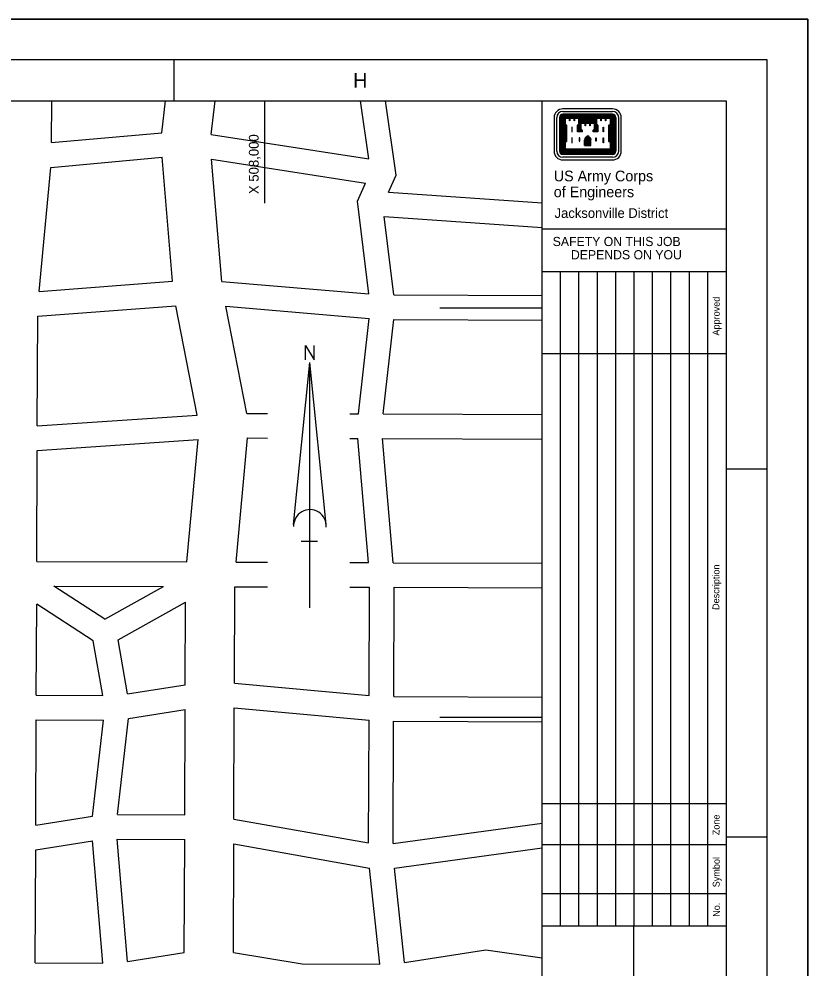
# Model space of a CAD drawing. Extents: x 501128 to 509328, y 1314906 to 1320706.
# Drawn here: x 507399 to 509328, y 1318384 to 1320706 of the extents above; entities that cross this region are included whole.
import ezdxf

# ---------------------------------------------------------------- set-up
doc = ezdxf.new("R2010")
doc.units = 0
for name, color, linetype in [('G-ANNO-SYMB', 7, 'Continuous'), ('G-ANNO-TEXT', 7, 'Continuous'), ('G-ANNO-TTLB', 7, 'Continuous'), ('Level 14', 7, 'Continuous'), ('Level 2', 7, 'Continuous'), ('Level 3', 7, 'Continuous'), ('Level 32', 7, 'Continuous')]:
    doc.layers.add(name, color=color, linetype=linetype)

msp = doc.modelspace()

# ---------------------------------------------------------------- linework, layer by layer
at = {"layer": 'G-ANNO-SYMB'}
for p, q in [((508850.3, 1320486.7), (508728.7, 1320486.7)), ((508728.7, 1320480.3), (508850.3, 1320480.3)), ((508850.3, 1320473.5), (508728.7, 1320473.5)), ((508707.3, 1320465.3), (508707.3, 1320383.3)), ((508713.7, 1320383.3), (508713.7, 1320465.3)), ((508720.7, 1320465.3), (508720.7, 1320383.3)), ((508722.5, 1320465.3), (508722.5, 1320383.3)), ((508724.1, 1320465.3), (508724.1, 1320383.3)), ((508725.9, 1320465.3), (508725.9, 1320383.3)), ((508727.7, 1320465.3), (508727.7, 1320383.3)), ((508850.3, 1320471.7), (508728.7, 1320471.7)), ((508850.3, 1320469.9), (508728.7, 1320469.9)), ((508850.3, 1320468.3), (508728.7, 1320468.3)), ((508850.3, 1320466.5), (508728.7, 1320466.5)), ((508729.5, 1320465.3), (508729.5, 1320383.9)), ((508731.1, 1320465.3), (508731.1, 1320385.7)), ((508770.9, 1320464.9), (508808.1, 1320464.9)), ((508770.9, 1320463.1), (508808.1, 1320463.1)), ((508770.9, 1320461.5), (508808.1, 1320461.5)), ((508770.9, 1320459.7), (508808.1, 1320459.7)), ((508770.9, 1320457.9), (508808.1, 1320457.9)), ((508770.9, 1320456.3), (508808.1, 1320456.3)), ((508770.9, 1320454.5), (508808.1, 1320454.5)), ((508847.9, 1320465.3), (508847.9, 1320385.7)), ((508849.5, 1320465.3), (508849.5, 1320383.9)), ((508851.3, 1320465.3), (508851.3, 1320383.3)), ((508853.1, 1320465.3), (508853.1, 1320383.3)), ((508854.7, 1320465.3), (508854.7, 1320383.3)), ((508856.5, 1320465.3), (508856.5, 1320383.3)), ((508858.3, 1320465.3), (508858.3, 1320383.3)), ((508865.1, 1320465.3), (508865.1, 1320383.3)), ((508871.7, 1320383.3), (508871.7, 1320465.3)), ((508732.5, 1320447.9), (508732.5, 1320405.9)), ((508734.3, 1320446.1), (508734.3, 1320407.9)), ((508844.7, 1320446.1), (508844.7, 1320407.9)), ((508846.5, 1320447.7), (508846.5, 1320406.1)), ((508781.5, 1320397.5), (508781.5, 1320410.9)), ((508783.1, 1320397.5), (508783.1, 1320410.9)), ((508784.9, 1320397.5), (508784.9, 1320410.9)), ((508786.7, 1320397.5), (508786.7, 1320410.9)), ((508788.3, 1320397.5), (508788.3, 1320410.9)), ((508790.7, 1320397.5), (508790.7, 1320410.9)), ((508792.3, 1320397.5), (508792.3, 1320410.9)), ((508794.1, 1320397.5), (508794.1, 1320410.9)), ((508795.9, 1320397.5), (508795.9, 1320410.9)), ((508797.5, 1320397.5), (508797.5, 1320410.9)), ((508850.3, 1320382.1), (508728.7, 1320382.1)), ((508850.3, 1320380.5), (508728.7, 1320380.5)), ((508849.5, 1320383.9), (508729.5, 1320383.9)), ((508847.9, 1320385.7), (508731.1, 1320385.7)), ((508781.5, 1320397.5), (508797.5, 1320397.5)), ((508850.3, 1320378.7), (508728.7, 1320378.7)), ((508850.3, 1320376.9), (508728.7, 1320376.9)), ((508850.3, 1320375.3), (508728.7, 1320375.3)), ((508850.3, 1320368.3), (508728.7, 1320368.3)), ((508728.7, 1320361.7), (508850.3, 1320361.7))]:
    msp.add_line(p, q, dxfattribs=at)
for points in [[(508732.5, 1320465.3), (508732.5, 1320449.5), (508735.9, 1320446.1), (508735.9, 1320407.9), (508732.5, 1320404.3), (508732.5, 1320386.9), (508846.5, 1320386.9), (508846.5, 1320404.3), (508842.9, 1320407.9), (508842.9, 1320446.1), (508846.5, 1320449.5), (508846.5, 1320465.3), (508831.5, 1320465.3), (508819.9, 1320465.3), (508809.1, 1320465.3), (508809.1, 1320449.5), (508812.9, 1320446.1), (508812.9, 1320432.1), (508804.5, 1320432.1), (508804.5, 1320433.5), (508808.1, 1320437.1), (508808.1, 1320452.7), (508793.1, 1320452.7), (508781.5, 1320452.7), (508770.9, 1320452.7), (508770.9, 1320437.1), (508774.5, 1320433.5), (508774.5, 1320432.1), (508766.1, 1320432.1), (508766.1, 1320446.1), (508769.7, 1320449.5), (508769.7, 1320465.3), (508754.7, 1320465.3), (508743.1, 1320465.3), (508732.5, 1320465.3)], [(508734.1, 1320463.5), (508734.1, 1320450.3), (508737.7, 1320446.7), (508737.7, 1320407.1), (508734.1, 1320403.5), (508734.1, 1320388.7), (508844.9, 1320388.7), (508844.9, 1320403.5), (508841.1, 1320407.1), (508841.1, 1320446.7), (508844.9, 1320450.3), (508844.9, 1320463.5), (508834.1, 1320463.5), (508834.1, 1320457.3), (508833.1, 1320457.3), (508833.1, 1320463.5), (508822.5, 1320463.5), (508822.5, 1320457.3), (508821.7, 1320457.3), (508821.7, 1320463.5), (508810.9, 1320463.5), (508810.9, 1320450.3), (508814.5, 1320446.7), (508814.5, 1320430.5), (508802.9, 1320430.5), (508802.9, 1320434.3), (508806.5, 1320437.9), (508806.5, 1320451.1), (508795.7, 1320451.1), (508795.7, 1320444.9), (508794.9, 1320444.9), (508794.9, 1320451.1), (508784.1, 1320451.1), (508784.1, 1320444.9), (508783.1, 1320444.9), (508783.1, 1320451.1), (508772.5, 1320451.1), (508772.5, 1320437.9), (508776.1, 1320434.3), (508776.1, 1320430.5), (508764.5, 1320430.5), (508764.5, 1320446.7), (508768.1, 1320450.3), (508768.1, 1320463.5), (508757.5, 1320463.5), (508757.5, 1320457.3), (508756.5, 1320457.3), (508756.5, 1320463.5), (508745.7, 1320463.5), (508745.7, 1320457.3), (508744.9, 1320457.3), (508744.9, 1320463.5), (508734.1, 1320463.5)], [(508750.5, 1320442.1), (508750.5, 1320430.5), (508751.7, 1320430.5), (508751.7, 1320442.1), (508750.5, 1320442.1)], [(508768.9, 1320446.3), (508767.9, 1320445.3), (508767.9, 1320433.9), (508771.7, 1320433.9), (508769.1, 1320436.5), (508769.1, 1320446.5)], [(508810.1, 1320446.3), (508811.1, 1320445.3), (508811.1, 1320433.9), (508807.5, 1320433.9), (508809.9, 1320436.5), (508809.9, 1320446.5)], [(508828.3, 1320442.1), (508828.3, 1320430.5), (508827.3, 1320430.5), (508827.3, 1320442.1), (508828.3, 1320442.1)], [(508750.5, 1320415.5), (508750.5, 1320403.7), (508751.7, 1320403.7), (508751.7, 1320415.5), (508750.5, 1320415.5)], [(508768.9, 1320415.5), (508768.9, 1320407.3), (508769.9, 1320407.3), (508769.9, 1320415.5), (508768.9, 1320415.5)], [(508810.1, 1320415.5), (508810.1, 1320407.3), (508809.1, 1320407.3), (508809.1, 1320415.5), (508810.1, 1320415.5)], [(508828.3, 1320415.5), (508828.3, 1320403.7), (508827.3, 1320403.7), (508827.3, 1320415.5), (508828.3, 1320415.5)]]:
    msp.add_lwpolyline(points, dxfattribs=at)
for centre, major_axis, start_param, end_param in [((508728.8, 1320465.3), (21.4, 0), 1.57078, 3.141576), ((508728.8, 1320465.3), (15, 0), 1.57078, 3.141576), ((508728.8, 1320465.3), (8.04, 0), 1.57078, 3.141576), ((508850.2, 1320465.3), (21.4, 0), 6.283169, 7.853965), ((508850.2, 1320465.3), (15, 0), 6.28317, 7.853966), ((508850.2, 1320465.3), (8.04, 0), 6.283169, 7.853965), ((508728.8, 1320465.3), (6.3, 0), 1.57078, 3.141576), ((508728.8, 1320465.3), (4.56, 0), 1.57078, 3.141576), ((508728.8, 1320465.3), (2.83, 0), 1.57078, 3.141576), ((508728.8, 1320465.3), (1.09, 0), 1.57078, 3.141576), ((508850.2, 1320465.3), (6.3, 0), 6.283169, 7.853965), ((508850.2, 1320465.3), (4.56, 0), 6.283169, 7.853965), ((508850.2, 1320465.3), (2.83, 0), 6.283169, 7.853965), ((508850.2, 1320465.3), (1.09, 0), 6.283169, 7.853965), ((508792.5, 1320410), (-11.1, 0), 4.985832, 6.214359), ((508792.5, 1320410), (-9.37, 0), 4.947465, 6.21436), ((508792.5, 1320410), (-7.63, 0), 4.947465, 6.21436), ((508792.5, 1320410), (-5.9, 0), 4.947465, 6.21436), ((508786.5, 1320410), (4.16, 0), 0.068794, 1.335689), ((508786.5, 1320410), (5.9, 0), 0.068794, 1.335689), ((508786.5, 1320410), (7.63, 0), 0.068795, 1.335689), ((508792.5, 1320410), (-4.16, 0), 4.947465, 6.214359), ((508786.5, 1320410), (9.37, 0), 0.068795, 1.335689), ((508786.5, 1320410), (11.1, 0), 0.068795, 1.29842), ((508728.8, 1320383.2), (-21.4, 0), 6.28317, 7.853966), ((508728.8, 1320383.2), (-15, 0), 6.28317, 7.853966), ((508728.8, 1320383.2), (-8.04, 0), 6.28317, 7.853966), ((508728.8, 1320383.2), (-6.3, 0), 6.28317, 7.853966), ((508728.8, 1320383.2), (-4.56, 0), 6.28317, 7.853966), ((508728.8, 1320383.2), (-2.83, 0), 6.28317, 7.853966), ((508728.8, 1320383.2), (-1.09, 0), 6.28317, 7.853966), ((508850.2, 1320383.2), (8.04, 0), 4.712373, 6.28317), ((508850.2, 1320383.2), (6.3, 0), 4.712373, 6.28317), ((508850.2, 1320383.2), (4.56, 0), 4.712373, 6.28317), ((508850.2, 1320383.2), (2.83, 0), 4.712373, 6.28317), ((508850.2, 1320383.2), (1.09, 0), 4.712373, 6.28317), ((508850.2, 1320383.2), (21.4, 0), 4.712373, 6.28317), ((508850.2, 1320383.2), (-15, 0), 1.570781, 3.141577)]:
    msp.add_ellipse(centre, major_axis=major_axis, ratio=0.99964, start_param=start_param, end_param=end_param, dxfattribs=at)
at = {"layer": 'G-ANNO-TTLB'}
for p, q in [((509228.1, 1320606.3), (501228.1, 1320606.3)), ((507778.1, 1320506.3), (507778.1, 1320606.3)), ((509228.1, 1315006.3), (509228.1, 1320606.3)), ((501478.1, 1320506.3), (509128.1, 1320506.3)), ((508678.1, 1315106.3), (508678.1, 1320506.3)), ((509128.1, 1320506.3), (509128.1, 1315106.3)), ((509128.1, 1320192.9), (508678.1, 1320192.9)), ((508723.1, 1318488.9), (508723.1, 1320088.7)), ((508768.1, 1318488.9), (508768.1, 1320088.7)), ((508813.1, 1318488.9), (508813.1, 1320088.7)), ((508858.1, 1318488.9), (508858.1, 1320088.7)), ((508903.1, 1318488.9), (508903.1, 1320088.7)), ((508948.1, 1318488.9), (508948.1, 1320088.7)), ((508993.1, 1318488.9), (508993.1, 1320088.7)), ((509038.1, 1318488.9), (509038.1, 1320088.7)), ((509083.1, 1318488.9), (509083.1, 1320088.7)), ((508678.1, 1319888.7), (509128.1, 1319888.7)), ((509228.1, 1319606.3), (509128.1, 1319606.3)), ((508678.1, 1318788.9), (509128.1, 1318788.9)), ((508678.1, 1318688.9), (509128.1, 1318688.9)), ((509228.1, 1318706.3), (509128.1, 1318706.3)), ((508678.1, 1318568.9), (509128.1, 1318568.9)), ((508901.5, 1318488.9), (508901.5, 1317449.1))]:
    msp.add_line(p, q, dxfattribs=at)
for points in [[(501128.1, 1314906.3), (509328.1, 1314906.3), (509328.1, 1320706.3), (501128.1, 1320706.3)], [(501128.1, 1314906.3), (509328.1, 1314906.3), (509328.1, 1320706.3), (501128.1, 1320706.3)], [(501128.1, 1320706.3), (509328.1, 1320706.3), (509328.1, 1314906.3), (501128.1, 1314906.3)]]:
    msp.add_lwpolyline(points, close=True, dxfattribs=at)
for points in [[(509278.1, 1320706.3), (509328.1, 1320706.3), (509328.1, 1320656.3)], [(509128.1, 1320088.7), (508678.1, 1320088.7)], [(509128.1, 1318488.9), (508678.1, 1318488.9)]]:
    msp.add_lwpolyline(points, dxfattribs=at)
at = {"layer": 'Level 14'}
for p, q in [((507478.7, 1320404.1), (507479.1, 1320506.3)), ((507748.5, 1320428.4), (507757.5, 1320506.3)), ((507868.8, 1320424.2), (507878.3, 1320506.3)), ((507774.6, 1320065.1), (507748.8, 1320368.2)), ((507895, 1320065), (507869.7, 1320363.4)), ((507448.4, 1320040.1), (507476.5, 1320343.7)), ((507834.2, 1319738.1), (507782.5, 1320005.6)), ((507955.7, 1319742.2), (507905, 1320004)), ((507443.8, 1319712.1), (507444.8, 1319979.7)), ((507809.2, 1319379.2), (507836.9, 1319678.1)), ((507929.7, 1319378.7), (507957.8, 1319682.2)), ((507442.5, 1319380.6), (507443.6, 1319651.9)), ((507925.7, 1319082.8), (507926.5, 1319318.7)), ((507441.3, 1319053.4), (507442.2, 1319276.3)), ((507805.6, 1319079.1), (507806.4, 1319281)), ((507804.4, 1318761.2), (507805.4, 1319018.3)), ((507924.4, 1318750.8), (507925.4, 1319022.6)), ((507440.1, 1318736.2), (507441.1, 1318993.4)), ((507803.2, 1318424.7), (507804.2, 1318701.2)), ((507923.2, 1318424.2), (507924.2, 1318689.9)), ((507438.8, 1318399), (507439.9, 1318675.4))]:
    msp.add_line(p, q, dxfattribs=at)
at = {"layer": 'Level 2'}
for p, q in [((508000, 1320256.3), (508000, 1320506.3)), ((508428.1, 1320000), (508678.1, 1320000)), ((508070.5, 1319471.1), (508110.3, 1319867.1)), ((508110.3, 1319267.1), (508110.3, 1319867.1)), ((508150.1, 1319471.1), (508110.3, 1319867.1)), ((508129.2, 1319429.1), (508089.2, 1319429.1)), ((508428.1, 1319000), (508678.1, 1319000))]:
    msp.add_line(p, q, dxfattribs=at)
msp.add_lwpolyline([(508099.2, 1319873.5), (508099.2, 1319908.5), (508121, 1319873.5), (508121, 1319908.5)], dxfattribs=at)
msp.add_arc((508110.3, 1319467.1), 40, 355.2984, 182.0673, dxfattribs=at)
at = {"layer": 'Level 32'}
for p, q in [((508254.5, 1320364.8), (508234.1, 1320506.3)), ((508320.9, 1320324.6), (508294.7, 1320506.3)), ((507478.7, 1320404.1), (507748.5, 1320428.4)), ((507868.8, 1320424.2), (508254.5, 1320364.8)), ((507476.5, 1320343.7), (507748.8, 1320368.2)), ((507869.7, 1320363.4), (508246.5, 1320305.3)), ((508302.4, 1320283.3), (508320.9, 1320324.6)), ((508226.6, 1320261), (508246.5, 1320305.3)), ((508302.4, 1320283.3), (508678.1, 1320257)), ((508254.5, 1320034.8), (508226.6, 1320261)), ((508315.3, 1320031.7), (508291.7, 1320223.9)), ((508291.7, 1320223.9), (508678.1, 1320196.9)), ((507448.4, 1320040.1), (507774.6, 1320065.1)), ((507895, 1320065), (508254.5, 1320034.8)), ((508315.3, 1320031.7), (508678.1, 1320030.3)), ((507444.8, 1319979.7), (507782.5, 1320005.6)), ((507905, 1320004), (508255.4, 1319974.5)), ((508228.7, 1319741.2), (508255.4, 1319974.5)), ((508289, 1319740.9), (508315.5, 1319971.7)), ((508315.5, 1319971.7), (508678.1, 1319970.3)), ((507443.8, 1319712.1), (507834.2, 1319738.1)), ((507955.7, 1319742.2), (508006.4, 1319742)), ((508208.1, 1319741.2), (508228.7, 1319741.2)), ((508289, 1319740.9), (508678.1, 1319739.5)), ((507443.6, 1319651.9), (507836.9, 1319678.1)), ((507957.8, 1319682.2), (508006.4, 1319682)), ((508208.1, 1319681.2), (508227.8, 1319681.2)), ((508253.6, 1319377.5), (508227.8, 1319681.2)), ((508313.9, 1319377.3), (508288.1, 1319680.9)), ((508288.1, 1319680.9), (508678.1, 1319679.5)), ((507442.5, 1319380.6), (507809.2, 1319379.2)), ((507929.7, 1319378.7), (508006.4, 1319378.4)), ((508208.1, 1319377.7), (508253.6, 1319377.5)), ((508313.9, 1319377.3), (508678.1, 1319375.9)), ((507609, 1319239.5), (507484.4, 1319320.4)), ((507484.4, 1319320.4), (507752.1, 1319319.4)), ((507609, 1319239.5), (507752.1, 1319319.4)), ((507926.5, 1319318.7), (508006.4, 1319318.4)), ((508208.1, 1319317.7), (508256.2, 1319317.5)), ((508255.2, 1319053), (508256.2, 1319317.5)), ((508315.2, 1319050.1), (508316.2, 1319317.3)), ((508316.2, 1319317.3), (508678.1, 1319315.9)), ((507580.5, 1319186.5), (507442.2, 1319276.3)), ((507641.1, 1319188.7), (507806.4, 1319281)), ((507603.8, 1319052.8), (507580.5, 1319186.5)), ((507664, 1319056.8), (507641.1, 1319188.7)), ((507925.7, 1319082.8), (508255.2, 1319053)), ((507664, 1319056.8), (507805.6, 1319079.1)), ((507441.3, 1319053.4), (507603.8, 1319052.8)), ((508315.2, 1319050.1), (508678.1, 1319048.7)), ((507666.7, 1318996.5), (507805.4, 1319018.3)), ((507925.4, 1319022.6), (508255, 1318992.8)), ((507441.1, 1318993.4), (507605.8, 1318992.7)), ((507578.9, 1318758), (507605.8, 1318992.7)), ((507639.7, 1318761.8), (507666.7, 1318996.5)), ((508253.9, 1318692.4), (508255, 1318992.8)), ((508313.9, 1318691.1), (508315, 1318990.1)), ((508315, 1318990.1), (508678.1, 1318988.7)), ((507440.1, 1318736.2), (507578.9, 1318758)), ((507639.7, 1318761.8), (507804.4, 1318761.2)), ((507924.4, 1318750.8), (508253.9, 1318692.4)), ((508313.9, 1318691.1), (508678.1, 1318740.9)), ((507439.9, 1318675.4), (507578.9, 1318697.3)), ((507604.3, 1318398.3), (507578.9, 1318697.3)), ((507664.2, 1318402.9), (507638.7, 1318701.8)), ((507638.7, 1318701.8), (507804.2, 1318701.2)), ((507924.2, 1318689.9), (508256.3, 1318631)), ((508316.7, 1318630.9), (508678.1, 1318680.4)), ((508281.5, 1318395.8), (508256.3, 1318631)), ((508341.4, 1318400.2), (508316.7, 1318630.9)), ((508341.4, 1318400.2), (508540.8, 1318431.5)), ((508540.8, 1318431.5), (508678.1, 1318411.7)), ((507664.2, 1318402.9), (507803.2, 1318424.7)), ((507923.2, 1318424.2), (508091.4, 1318396.5)), ((507438.8, 1318399), (507604.3, 1318398.3)), ((508091.4, 1318396.5), (508281.5, 1318395.8))]:
    msp.add_line(p, q, dxfattribs=at)

# ---------------------------------------------------------------- texts
at = {"layer": 'G-ANNO-TEXT'}
for s, height, p in [('US Army Corps', 26.172, (508706.5, 1320309.5)), ('of Engineers', 26.172, (508706.5, 1320270.7)), ('Jacksonville District', 23.8, (508708.5, 1320220.1)), ('SAFETY ON THIS JOB', 22.397, (508703.9, 1320151.3)), ('DEPENDS ON YOU', 22.397, (508748.5, 1320118.9))]:
    msp.add_text(s, height=height, dxfattribs=at).set_placement(p)
for s, height, p in [('Approved', 16.6, (509111.7, 1319932.5)), ('Description', 16.598, (509111.1, 1319261.9)), ('Zone', 16.6, (509111.7, 1318711.1)), ('Symbol', 16.6, (509111.9, 1318583.9)), ('No.', 16.6, (509112.5, 1318511.7))]:
    msp.add_text(s, height=height, rotation=89.6609, dxfattribs=at).set_placement(p)
at = {"layer": 'G-ANNO-TTLB'}
msp.add_text('H', height=35.7, dxfattribs=at).set_placement((508216.1, 1320538.5))
at = {"layer": 'Level 3'}
msp.add_text('X 508,000', height=24, rotation=90, dxfattribs=at).set_placement((507985, 1320278.3))

doc.saveas('drawing.dxf')
